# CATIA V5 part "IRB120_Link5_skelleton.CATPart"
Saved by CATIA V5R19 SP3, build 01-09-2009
Part number: IRB120_Link5_skelleton
Bounding box of the stored display mesh (mm): x 0 to 50, y 0 to 50, z 0 to 0
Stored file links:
  Z:\Projects\ABB_Robotics\ABB LIB\V5\V5PARTS\ABB\120\IRB120_Link5_skelleton.CATPart
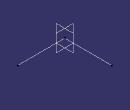
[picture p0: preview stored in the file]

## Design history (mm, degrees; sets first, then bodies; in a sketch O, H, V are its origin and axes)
Body1 (main body)
  Line1: type PtPt, FirstPoint {point type Coord, X 0, Y 0, Z 0}, SecondPoint {point type Coord, X 0, Y 50, Z 0, RefPoint {point type Coord, X 0, Y 0, Z 0}}
  Line2: type PtPt, FirstPoint vertex of Line1, SecondPoint {point type Coord, X 50, Y 0, Z 0, RefPoint vertex of Line1}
